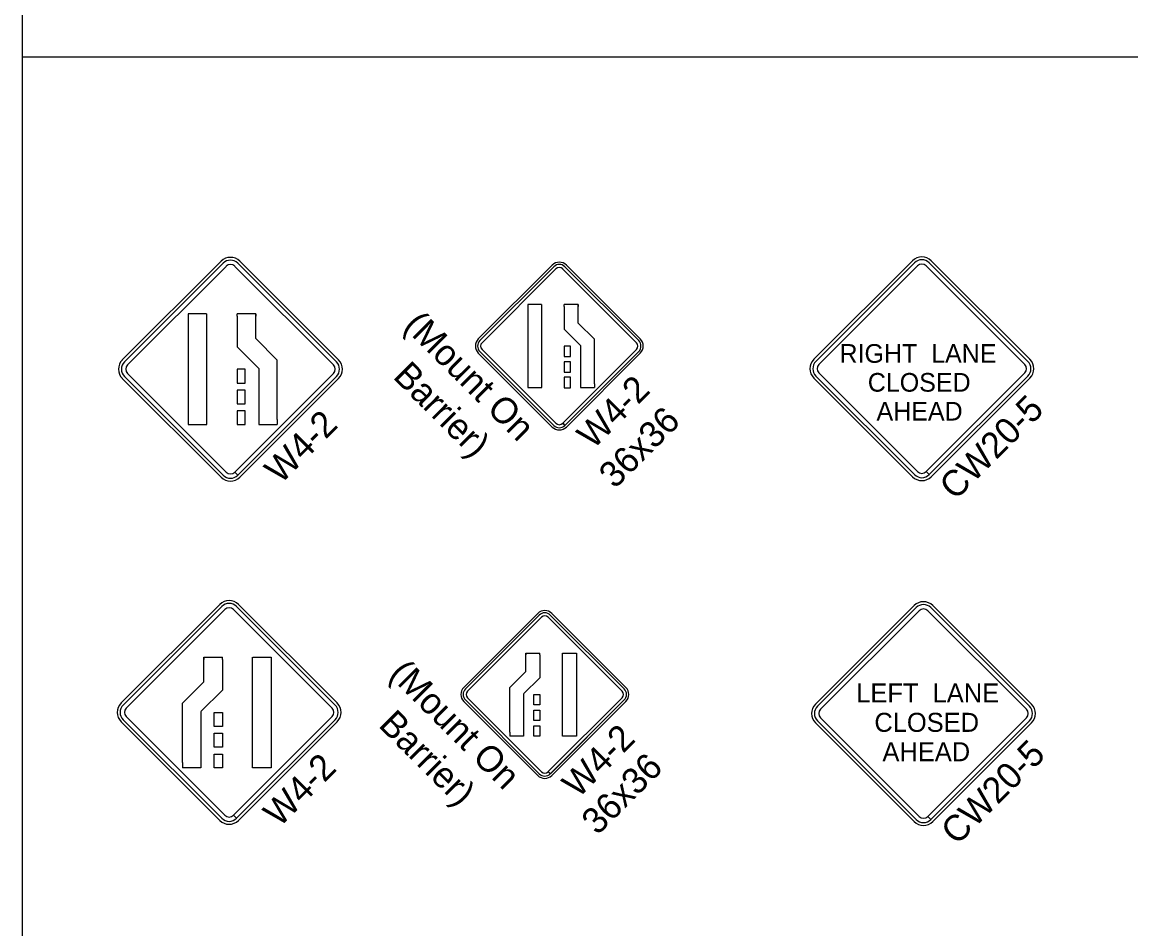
# Model space of a CAD drawing. Extents: x 1458 to 4498, y 17709 to 24109.
# Drawn here: x 1458 to 2099, y 22649 to 23174 of the extents above; entities that cross this region are included whole.
import ezdxf

# ---------------------------------------------------------------- set-up
doc = ezdxf.new("R2010")
doc.units = 0
doc.layers.add('P_ODOT_PLAN_TBlock', color=7, linetype='Continuous')
doc.layers.add('P_TRAF_TCP_General', color=7, linetype='Continuous')

msp = doc.modelspace()

# ---------------------------------------------------------------- linework, layer by layer
at = {"layer": 'P_ODOT_PLAN_TBlock'}
msp.add_line((1458.44, 23153.55), (3578.44, 23153.55), dxfattribs=at)
at = {"layer": 'P_TRAF_TCP_General'}
for p, q in [((1573.31, 23035.35), (1516.3, 22978.35)), ((1574.49, 23034.17), (1517.49, 22977.16)), ((1574.49, 23034.17), (1517.49, 22977.16)), ((1519.25, 22975.4), (1576.26, 23032.4)), ((1519.25, 22975.4), (1576.26, 23032.4)), ((1519.25, 22975.4), (1576.26, 23032.4)), ((1581.21, 23032.4), (1638.21, 22975.4)), ((1581.21, 23032.4), (1638.21, 22975.4)), ((1581.21, 23032.4), (1638.21, 22975.4)), ((1639.98, 22977.16), (1582.97, 23034.17)), ((1639.98, 22977.16), (1582.97, 23034.17)), ((1641.16, 22978.35), (1584.16, 23035.35)), ((1764.64, 23033.11), (1721.95, 22990.41)), ((1765.56, 23032.19), (1722.86, 22989.5)), ((1765.56, 23032.19), (1722.86, 22989.5)), ((1814.61, 22989.5), (1771.92, 23032.19)), ((1814.61, 22989.5), (1771.92, 23032.19)), ((1815.53, 22990.41), (1772.84, 23033.11)), ((1972.8, 23035.66), (1915.79, 22978.65)), ((1973.98, 23034.47), (1916.98, 22977.47)), ((1973.98, 23034.47), (1916.98, 22977.47)), ((1973.98, 23034.47), (1916.98, 22977.47)), ((1918.74, 22975.7), (1975.75, 23032.71)), ((1918.74, 22975.7), (1975.75, 23032.71)), ((1980.7, 23032.71), (2037.7, 22975.7)), ((1980.7, 23032.71), (2037.7, 22975.7)), ((2039.47, 22977.47), (1982.46, 23034.47)), ((2039.47, 22977.47), (1982.46, 23034.47)), ((2039.47, 22977.47), (1982.46, 23034.47)), ((2040.65, 22978.65), (1983.65, 23035.66)), ((1724.1, 22988.26), (1766.79, 23030.95)), ((1770.68, 23030.95), (1813.37, 22988.26)), ((1758.43, 23010.27), (1750.49, 23010.27)), ((1750.49, 23010.27), (1750.49, 22962.29)), ((1758.55, 22986.28), (1758.55, 23010.27)), ((1779.69, 23010.27), (1771.63, 23010.27)), ((1771.63, 23009.25), (1771.63, 23010.27)), ((1771.63, 23009.25), (1771.63, 22996)), ((1771.63, 23009.25), (1771.63, 22996)), ((1779.69, 23010.27), (1779.69, 23009.25)), ((1779.69, 22999.6), (1779.69, 23010.27)), ((1565, 23004.88), (1554.42, 23004.88)), ((1554.42, 23004.88), (1554.42, 22940.95)), ((1565.16, 22972.92), (1565.16, 23004.88)), ((1593.33, 23004.88), (1582.59, 23004.88)), ((1582.59, 23003.53), (1582.59, 23004.88)), ((1582.59, 23003.53), (1582.59, 22985.87)), ((1582.59, 23003.53), (1582.59, 22985.87)), ((1593.33, 23004.88), (1593.33, 23003.53)), ((1593.33, 22990.67), (1593.33, 23004.88)), ((1789, 22990.26), (1779.69, 22999.6)), ((1771.63, 22996), (1781.01, 22986.62)), ((1605.73, 22978.22), (1593.33, 22990.67)), ((1781.04, 22986.58), (1781.04, 22971.02)), ((1789, 22988.02), (1789, 22990.26)), ((1789, 22971.02), (1789, 22988.02)), ((1582.59, 22985.87), (1595.08, 22973.38)), ((1721.95, 22982.21), (1764.64, 22939.52)), ((1722.86, 22983.13), (1765.56, 22940.44)), ((1722.86, 22983.13), (1765.56, 22940.44)), ((1766.79, 22941.68), (1724.1, 22984.37)), ((1758.55, 22962.29), (1758.55, 22986.28)), ((1813.37, 22984.37), (1770.69, 22941.69)), ((1775.18, 22986.25), (1771.61, 22986.25)), ((1771.61, 22986.25), (1771.61, 22980.26)), ((1771.61, 22980.26), (1775.18, 22980.26)), ((1771.92, 22940.44), (1814.61, 22983.13)), ((1771.93, 22940.45), (1814.61, 22983.13)), ((1772.84, 22939.52), (1815.53, 22982.21)), ((1775.18, 22980.26), (1775.18, 22986.25)), ((1605.73, 22975.24), (1605.73, 22978.22)), ((1605.73, 22952.59), (1605.73, 22975.24)), ((1775.18, 22977.26), (1771.61, 22977.26)), ((1771.61, 22977.26), (1771.61, 22971.26)), ((1775.18, 22971.26), (1775.18, 22977.26)), ((1516.3, 22967.5), (1573.31, 22910.49)), ((1517.49, 22968.68), (1574.49, 22911.68)), ((1517.49, 22968.68), (1574.49, 22911.68)), ((1517.49, 22968.68), (1574.49, 22911.68)), ((1576.26, 22913.44), (1519.25, 22970.45)), ((1565.16, 22940.95), (1565.16, 22972.92)), ((1638.21, 22970.45), (1581.23, 22913.46)), ((1638.21, 22970.45), (1581.23, 22913.46)), ((1638.21, 22970.45), (1581.23, 22913.46)), ((1587.31, 22972.89), (1582.57, 22972.89)), ((1582.57, 22972.89), (1582.57, 22964.9)), ((1582.99, 22911.69), (1639.98, 22968.68)), ((1582.99, 22911.69), (1639.98, 22968.68)), ((1584.16, 22910.49), (1641.16, 22967.5)), ((1587.31, 22964.9), (1587.31, 22972.89)), ((1595.13, 22973.32), (1595.13, 22952.59)), ((1771.61, 22971.26), (1775.18, 22971.26)), ((1775.18, 22968.26), (1771.61, 22968.26)), ((1771.61, 22968.26), (1771.61, 22962.26)), ((1775.18, 22962.26), (1775.18, 22968.26)), ((1781.04, 22971.02), (1781.04, 22964.53)), ((1789, 22964.53), (1789, 22971.02)), ((1915.79, 22967.8), (1972.8, 22910.8)), ((1916.98, 22968.99), (1973.98, 22911.98)), ((1916.98, 22968.99), (1973.98, 22911.98)), ((1916.98, 22968.99), (1973.98, 22911.98)), ((1975.75, 22913.75), (1918.74, 22970.75)), ((1975.75, 22913.75), (1918.74, 22970.75)), ((2037.7, 22970.75), (1980.71, 22913.77)), ((2037.7, 22970.75), (1980.71, 22913.77)), ((1982.46, 22911.98), (2039.47, 22968.99)), ((1982.48, 22912), (2039.47, 22968.99)), ((1982.48, 22912), (2039.47, 22968.99)), ((1983.65, 22910.8), (2040.65, 22967.8)), ((1582.57, 22964.9), (1587.31, 22964.9)), ((1587.31, 22960.9), (1582.57, 22960.9)), ((1582.57, 22960.9), (1582.57, 22952.91)), ((1587.31, 22952.91), (1587.31, 22960.9)), ((1750.49, 22962.29), (1758.55, 22962.29)), ((1771.61, 22962.26), (1775.18, 22962.26)), ((1781.04, 22964.53), (1781.04, 22962.29)), ((1781.04, 22962.29), (1789, 22962.29)), ((1789, 22964.53), (1789, 22962.29)), ((1582.57, 22952.91), (1587.31, 22952.91)), ((1587.31, 22948.91), (1582.57, 22948.91)), ((1582.57, 22948.91), (1582.57, 22940.92)), ((1587.31, 22940.92), (1587.31, 22948.91)), ((1595.13, 22952.59), (1595.13, 22943.93)), ((1605.73, 22943.93), (1605.73, 22952.59)), ((1595.13, 22943.93), (1595.13, 22940.95)), ((1605.73, 22943.93), (1605.73, 22940.95)), ((1771.92, 22940.44), (1770.68, 22941.68)), ((1770.69, 22941.69), (1771.93, 22940.45)), ((1554.42, 22940.95), (1565.16, 22940.95)), ((1582.57, 22940.92), (1587.31, 22940.92)), ((1595.13, 22940.95), (1605.73, 22940.95)), ((1582.97, 22911.68), (1581.21, 22913.44)), ((1582.97, 22911.68), (1581.21, 22913.44)), ((1582.97, 22911.68), (1581.21, 22913.44)), ((1581.23, 22913.46), (1582.99, 22911.69)), ((1581.23, 22913.46), (1582.99, 22911.69)), ((1581.23, 22913.46), (1582.99, 22911.69)), ((1982.46, 22911.98), (1980.7, 22913.75)), ((1982.46, 22911.98), (1980.7, 22913.75)), ((1980.71, 22913.77), (1982.48, 22912)), ((1980.71, 22913.77), (1982.48, 22912)), ((1572.56, 22837), (1515.55, 22779.99)), ((1573.74, 22835.81), (1516.74, 22778.81)), ((1573.74, 22835.81), (1516.74, 22778.81)), ((1518.5, 22777.04), (1575.51, 22834.05)), ((1518.5, 22777.04), (1575.51, 22834.05)), ((1580.46, 22834.05), (1637.46, 22777.04)), ((1580.46, 22834.05), (1637.46, 22777.04)), ((1639.23, 22778.81), (1582.22, 22835.81)), ((1639.23, 22778.81), (1582.22, 22835.81)), ((1640.41, 22779.99), (1583.41, 22837)), ((1973.68, 22836.29), (1916.68, 22779.28)), ((1974.87, 22835.1), (1917.86, 22778.1)), ((1974.87, 22835.1), (1917.86, 22778.1)), ((1974.87, 22835.1), (1917.86, 22778.1)), ((1919.63, 22776.33), (1976.63, 22833.34)), ((1919.63, 22776.33), (1976.63, 22833.34)), ((1981.58, 22833.34), (2038.59, 22776.33)), ((1981.58, 22833.34), (2038.59, 22776.33)), ((2040.35, 22778.1), (1983.35, 22835.1)), ((2040.35, 22778.1), (1983.35, 22835.1)), ((2040.35, 22778.1), (1983.35, 22835.1)), ((2041.54, 22779.28), (1984.53, 22836.29)), ((1756.26, 22831.71), (1713.57, 22789.02)), ((1757.18, 22830.79), (1714.49, 22788.1)), ((1757.18, 22830.79), (1714.49, 22788.1)), ((1715.73, 22786.86), (1758.42, 22829.55)), ((1762.31, 22829.55), (1805, 22786.86)), ((1806.24, 22788.1), (1763.55, 22830.79)), ((1806.24, 22788.1), (1763.55, 22830.79)), ((1807.16, 22789.02), (1764.46, 22831.71)), ((1749.41, 22808.87), (1749.41, 22807.86)), ((1749.41, 22798.2), (1749.41, 22808.87)), ((1749.41, 22808.87), (1757.47, 22808.87)), ((1757.47, 22807.86), (1757.47, 22808.87)), ((1757.47, 22807.86), (1757.47, 22794.6)), ((1757.47, 22807.86), (1757.47, 22794.6)), ((1770.55, 22784.88), (1770.55, 22808.87)), ((1770.67, 22808.87), (1778.61, 22808.87)), ((1778.61, 22808.87), (1778.61, 22760.89)), ((1563.38, 22806.51), (1563.38, 22805.15)), ((1563.38, 22792.28), (1563.38, 22806.51)), ((1563.38, 22806.51), (1574.12, 22806.51)), ((1574.12, 22805.15), (1574.12, 22806.51)), ((1574.12, 22805.15), (1574.12, 22787.48)), ((1574.12, 22805.15), (1574.12, 22787.48)), ((1591.57, 22774.52), (1591.57, 22806.51)), ((1591.72, 22806.51), (1602.31, 22806.51)), ((1602.31, 22806.51), (1602.31, 22742.53)), ((1740.11, 22788.86), (1749.41, 22798.2)), ((1757.47, 22794.6), (1748.09, 22785.22)), ((1550.97, 22779.83), (1563.38, 22792.28)), ((1740.11, 22786.63), (1740.11, 22788.86)), ((1574.12, 22787.48), (1561.62, 22774.98)), ((1714.49, 22781.74), (1757.18, 22739.04)), ((1714.49, 22781.74), (1757.18, 22739.04)), ((1758.42, 22740.28), (1715.73, 22782.97)), ((1740.11, 22769.63), (1740.11, 22786.63)), ((1748.06, 22785.18), (1748.06, 22769.63)), ((1753.93, 22778.86), (1753.93, 22784.86)), ((1753.93, 22784.86), (1757.49, 22784.86)), ((1757.49, 22784.86), (1757.49, 22778.86)), ((1805, 22782.97), (1762.32, 22740.29)), ((1763.55, 22739.04), (1806.24, 22781.74)), ((1763.56, 22739.06), (1806.24, 22781.74)), ((1770.55, 22760.89), (1770.55, 22784.88)), ((1550.97, 22776.85), (1550.97, 22779.83)), ((1550.97, 22754.18), (1550.97, 22776.85)), ((1713.57, 22780.82), (1756.26, 22738.12)), ((1757.49, 22778.86), (1753.93, 22778.86)), ((1753.93, 22769.86), (1753.93, 22775.86)), ((1753.93, 22775.86), (1757.49, 22775.86)), ((1757.49, 22775.86), (1757.49, 22769.86)), ((1764.47, 22738.13), (1807.16, 22780.82)), ((1515.55, 22769.14), (1572.56, 22712.14)), ((1516.74, 22770.33), (1573.74, 22713.32)), ((1516.74, 22770.33), (1573.74, 22713.32)), ((1575.51, 22715.09), (1518.5, 22772.09)), ((1561.57, 22774.92), (1561.57, 22754.18)), ((1569.4, 22766.49), (1569.4, 22774.49)), ((1569.4, 22774.49), (1574.15, 22774.49)), ((1574.15, 22774.49), (1574.15, 22766.49)), ((1637.46, 22772.09), (1580.47, 22715.11)), ((1637.46, 22772.09), (1580.47, 22715.11)), ((1582.24, 22713.34), (1639.23, 22770.33)), ((1582.24, 22713.34), (1639.23, 22770.33)), ((1583.41, 22712.14), (1640.41, 22769.14)), ((1591.57, 22742.53), (1591.57, 22774.52)), ((1740.11, 22763.13), (1740.11, 22769.63)), ((1748.06, 22769.63), (1748.06, 22763.13)), ((1757.49, 22769.86), (1753.93, 22769.86)), ((1917.86, 22769.62), (1974.87, 22712.61)), ((1917.86, 22769.62), (1974.87, 22712.61)), ((1917.86, 22769.62), (1974.87, 22712.61)), ((1976.63, 22714.38), (1919.63, 22771.38)), ((1976.63, 22714.38), (1919.63, 22771.38)), ((2038.59, 22771.38), (1981.6, 22714.4)), ((2038.59, 22771.38), (1981.6, 22714.4)), ((1983.35, 22712.61), (2040.35, 22769.62)), ((1983.37, 22712.63), (2040.35, 22769.62)), ((1983.37, 22712.63), (2040.35, 22769.62)), ((1574.15, 22766.49), (1569.4, 22766.49)), ((1569.4, 22754.5), (1569.4, 22762.49)), ((1569.4, 22762.49), (1574.15, 22762.49)), ((1574.15, 22762.49), (1574.15, 22754.5)), ((1740.11, 22763.13), (1740.11, 22760.89)), ((1748.06, 22763.13), (1748.06, 22760.89)), ((1753.93, 22760.87), (1753.93, 22766.86)), ((1753.93, 22766.86), (1757.49, 22766.86)), ((1757.49, 22766.86), (1757.49, 22760.87)), ((1916.68, 22768.43), (1973.68, 22711.43)), ((1984.53, 22711.43), (2041.54, 22768.43)), ((1748.06, 22760.89), (1740.11, 22760.89)), ((1757.49, 22760.87), (1753.93, 22760.87)), ((1778.61, 22760.89), (1770.55, 22760.89)), ((1550.97, 22745.52), (1550.97, 22754.18)), ((1561.57, 22754.18), (1561.57, 22745.52)), ((1574.15, 22754.5), (1569.4, 22754.5)), ((1569.4, 22742.5), (1569.4, 22750.5)), ((1569.4, 22750.5), (1574.15, 22750.5)), ((1574.15, 22750.5), (1574.15, 22742.5)), ((1550.97, 22745.52), (1550.97, 22742.53)), ((1561.57, 22745.52), (1561.57, 22742.53)), ((1561.57, 22742.53), (1550.97, 22742.53)), ((1574.15, 22742.5), (1569.4, 22742.5)), ((1602.31, 22742.53), (1591.57, 22742.53)), ((1763.55, 22739.04), (1762.31, 22740.28)), ((1762.32, 22740.29), (1763.56, 22739.06)), ((1582.22, 22713.32), (1580.46, 22715.09)), ((1582.22, 22713.32), (1580.46, 22715.09)), ((1580.47, 22715.11), (1582.24, 22713.34)), ((1580.47, 22715.11), (1582.24, 22713.34)), ((1983.35, 22712.61), (1981.58, 22714.38)), ((1983.35, 22712.61), (1981.58, 22714.38)), ((1981.6, 22714.4), (1983.37, 22712.63)), ((1981.6, 22714.4), (1983.37, 22712.63))]:
    msp.add_line(p, q, dxfattribs=at)
msp.add_lwpolyline([(4498.44, 24109.14), (1458.44, 24109.14), (1458.44, 22109.14), (4498.44, 22109.14)], close=True, dxfattribs=at)
for centre, radius, start, end in [((1978.22, 23030.23), 7.67, 45, 135), ((1578.73, 23029.93), 7.67, 45, 135), ((1578.73, 23029.93), 6, 45, 135), ((1578.73, 23029.93), 6, 45, 135), ((1578.73, 23029.93), 3.5, 45, 135), ((1578.73, 23029.93), 3.5, 45, 135), ((1578.73, 23029.93), 3.5, 45, 135), ((1768.74, 23029.01), 5.8, 45, 135), ((1768.74, 23029.01), 4.5, 45, 135), ((1768.74, 23029.01), 4.5, 45, 135), ((1768.74, 23029.01), 2.75, 45, 135), ((1978.22, 23030.23), 6, 45, 135), ((1978.22, 23030.23), 6, 45, 135), ((1978.22, 23030.23), 6, 45, 135), ((1978.22, 23030.23), 3.5, 45, 135), ((1978.22, 23030.23), 3.5, 45, 135), ((1726.05, 22986.31), 5.8, 135, 225), ((1726.05, 22986.31), 4.5, 135, 225), ((1726.05, 22986.31), 4.5, 135, 225), ((1726.05, 22986.31), 2.75, 135, 225), ((1811.43, 22986.31), 2.75, 315, 45), ((1811.43, 22986.31), 4.5, 315, 45), ((1811.43, 22986.31), 4.5, 315, 45), ((1811.43, 22986.31), 5.8, 315, 45), ((1521.73, 22972.92), 7.67, 135, 225), ((1521.73, 22972.92), 6, 135, 225), ((1521.73, 22972.92), 6, 135, 225), ((1521.73, 22972.92), 3.5, 135, 225), ((1521.73, 22972.92), 3.5, 135, 225), ((1521.73, 22972.92), 3.5, 135, 225), ((1635.74, 22972.92), 3.5, 315, 45), ((1635.74, 22972.92), 3.5, 315, 45), ((1635.74, 22972.92), 3.5, 315, 45), ((1635.74, 22972.92), 6, 315, 45), ((1635.74, 22972.92), 6, 315, 45), ((1635.74, 22972.92), 7.67, 315, 45), ((1921.22, 22973.23), 7.67, 135, 225), ((1921.22, 22973.23), 6, 135, 225), ((1921.22, 22973.23), 6, 135, 225), ((1921.22, 22973.23), 6, 135, 225), ((1921.22, 22973.23), 3.5, 135, 225), ((1921.22, 22973.23), 3.5, 135, 225), ((2035.23, 22973.23), 3.5, 315, 45), ((2035.23, 22973.23), 3.5, 315, 45), ((2035.23, 22973.23), 6, 315, 45), ((2035.23, 22973.23), 6, 315, 45), ((2035.23, 22973.23), 6, 315, 45), ((2035.23, 22973.23), 7.67, 315, 45), ((1768.74, 22943.62), 2.75, 225, 315), ((1768.74, 22943.62), 5.8, 225, 315), ((1768.74, 22943.62), 4.5, 225, 315), ((1768.74, 22943.62), 4.5, 225, 315), ((1578.73, 22915.92), 7.67, 225, 315), ((1578.73, 22915.92), 6, 225, 315), ((1578.73, 22915.92), 6, 225, 315), ((1578.73, 22915.92), 3.5, 225, 315), ((1578.73, 22915.92), 3.5, 225, 315), ((1578.73, 22915.92), 3.5, 225, 315), ((1978.22, 22916.22), 7.67, 225, 315), ((1978.22, 22916.22), 6, 225, 315), ((1978.22, 22916.22), 6, 225, 315), ((1978.22, 22916.22), 6, 225, 315), ((1978.22, 22916.22), 3.5, 225, 315), ((1978.22, 22916.22), 3.5, 225, 315), ((1577.98, 22831.57), 7.67, 45, 135), ((1577.98, 22831.57), 6, 45, 135), ((1577.98, 22831.57), 6, 45, 135), ((1577.98, 22831.57), 3.5, 45, 135), ((1577.98, 22831.57), 3.5, 45, 135), ((1760.36, 22827.61), 5.8, 45, 135), ((1979.11, 22830.86), 7.67, 45, 135), ((1979.11, 22830.86), 6, 45, 135), ((1979.11, 22830.86), 6, 45, 135), ((1979.11, 22830.86), 6, 45, 135), ((1979.11, 22830.86), 3.5, 45, 135), ((1979.11, 22830.86), 3.5, 45, 135), ((1760.36, 22827.61), 4.5, 45, 135), ((1760.36, 22827.61), 4.5, 45, 135), ((1760.36, 22827.61), 2.75, 45, 135), ((1717.67, 22784.92), 5.8, 135, 225), ((1717.67, 22784.92), 4.5, 135, 225), ((1717.67, 22784.92), 4.5, 135, 225), ((1803.06, 22784.92), 4.5, 315, 45), ((1803.06, 22784.92), 4.5, 315, 45), ((1803.06, 22784.92), 5.8, 315, 45), ((1717.67, 22784.92), 2.75, 135, 225), ((1803.06, 22784.92), 2.75, 315, 45), ((1520.98, 22774.57), 7.67, 135, 225), ((1520.98, 22774.57), 6, 135, 225), ((1520.98, 22774.57), 6, 135, 225), ((1520.98, 22774.57), 3.5, 135, 225), ((1520.98, 22774.57), 3.5, 135, 225), ((1634.99, 22774.57), 3.5, 315, 45), ((1634.99, 22774.57), 3.5, 315, 45), ((1634.99, 22774.57), 6, 315, 45), ((1634.99, 22774.57), 6, 315, 45), ((1634.99, 22774.57), 7.67, 315, 45), ((1922.1, 22773.86), 7.67, 135, 225), ((1922.1, 22773.86), 6, 135, 225), ((1922.1, 22773.86), 6, 135, 225), ((1922.1, 22773.86), 6, 135, 225), ((1922.1, 22773.86), 3.5, 135, 225), ((1922.1, 22773.86), 3.5, 135, 225), ((2036.11, 22773.86), 3.5, 315, 45), ((2036.11, 22773.86), 3.5, 315, 45), ((2036.11, 22773.86), 6, 315, 45), ((2036.11, 22773.86), 6, 315, 45), ((2036.11, 22773.86), 6, 315, 45), ((2036.11, 22773.86), 7.67, 315, 45), ((1760.36, 22742.22), 5.8, 225, 315), ((1760.36, 22742.22), 4.5, 225, 315), ((1760.36, 22742.22), 4.5, 225, 315), ((1760.36, 22742.22), 2.75, 225, 315), ((1577.98, 22717.56), 7.67, 225, 315), ((1577.98, 22717.56), 6, 225, 315), ((1577.98, 22717.56), 6, 225, 315), ((1577.98, 22717.56), 3.5, 225, 315), ((1577.98, 22717.56), 3.5, 225, 315), ((1979.11, 22716.85), 7.67, 225, 315), ((1979.11, 22716.85), 6, 225, 315), ((1979.11, 22716.85), 6, 225, 315), ((1979.11, 22716.85), 6, 225, 315), ((1979.11, 22716.85), 3.5, 225, 315), ((1979.11, 22716.85), 3.5, 225, 315)]:
    msp.add_arc(centre, radius, start, end, dxfattribs=at)

# ---------------------------------------------------------------- texts
for s, rotation, p in [('(Mount On', 315, (1678.18, 22997.31)), ('Barrier)', 315, (1672.07, 22968.08)), ('W4-2', 45, (1788.23, 22926.12)), ('CW20-5', 45, (1997.51, 22896.64)), ('W4-2', 45, (1607.72, 22906.03)), ('36x36', 45, (1800.81, 22903.35)), ('(Mount On', 315, (1669.81, 22795.91)), ('Barrier)', 315, (1663.69, 22766.68)), ('W4-2', 45, (1779.6, 22724.46)), ('CW20-5', 45, (1998.4, 22697.27)), ('W4-2', 45, (1606.97, 22707.68)), ('36x36', 45, (1790.77, 22703.11))]:
    msp.add_text(s, height=14.994, rotation=rotation, dxfattribs=at).set_placement(p)
for s, height, p in [('RIGHT  LANE', 10.8, (1930.61, 22976.64)), ('CLOSED', 10.8, (1946.95, 22959.95)), ('AHEAD', 10.8, (1951.98, 22943.26)), ('LEFT  LANE', 10.996, (1940.28, 22780.3)), ('CLOSED', 10.996, (1950.76, 22763.31)), ('AHEAD', 10.996, (1955.42, 22746.32))]:
    msp.add_text(s, height=height, dxfattribs=at).set_placement(p)

doc.saveas('drawing.dxf')
